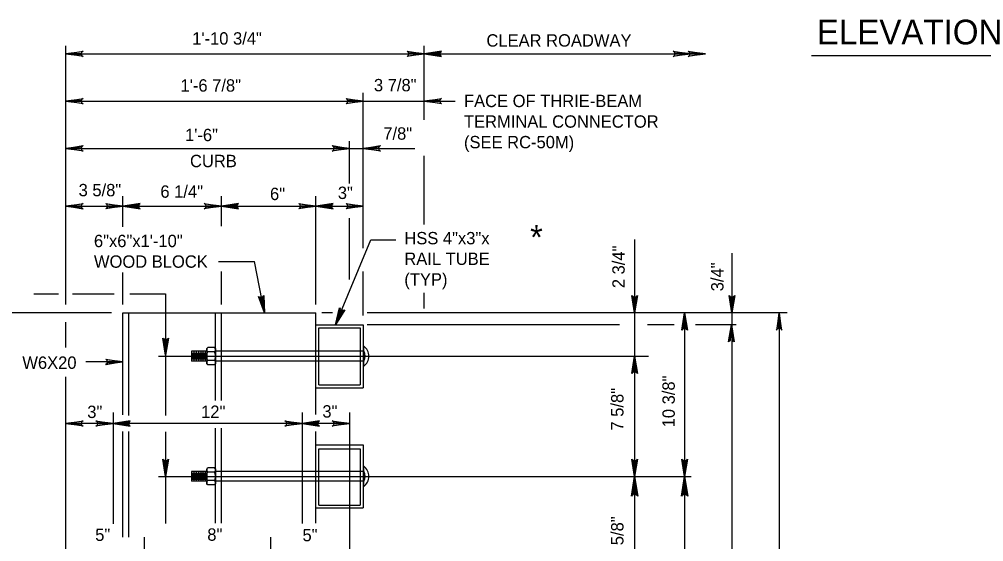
# Model space of a CAD drawing. Extents: x 641054 to 641910, y 298137 to 299325.
# Drawn here: x 641174.5 to 641408.6, y 298908.1 to 299034.9 of the extents above; entities that cross this region are included whole.
import ezdxf

# ---------------------------------------------------------------- set-up
doc = ezdxf.new("R2010")
doc.units = 0
for name, color, linetype in [('1', 7, 'Continuous'), ('2', 7, 'Continuous'), ('S-STEL', 7, 'Continuous')]:
    doc.layers.add(name, color=color, linetype=linetype)

msp = doc.modelspace()

# ---------------------------------------------------------------- linework, layer by layer
at = {"layer": '1'}
for p, q in [((641185.81, 298965.69), (641185.81, 299028.44)), ((641272.83, 299010.46), (641272.83, 299028.44)), ((641185.81, 299026.49), (641341.06, 299026.49)), ((641258.01, 298979.34), (641258.01, 299016.98)), ((641185.81, 299015.01), (641280.3, 299015.01)), ((641185.81, 299003.53), (641270.5, 299003.53)), ((641254.66, 298995.06), (641254.66, 299005.33)), ((641272.83, 298985.11), (641272.83, 299001.75)), ((641199.67, 298984.49), (641199.67, 298991.92)), ((641223.58, 298984.63), (641223.58, 298991.92)), ((641246.53, 298965.69), (641246.53, 298991.92)), ((641185.81, 298989.5), (641258.01, 298989.5)), ((641254.66, 298971.7), (641254.66, 298986.61)), ((641251.29, 298960.76), (641259.85, 298981.32)), ((641259.85, 298981.32), (641265.95, 298981.32)), ((641323.89, 298981.43), (641323.89, 298843.61)), ((641347.51, 298978.15), (641347.51, 298843.61)), ((641222.86, 298976.11), (641231.63, 298976.11)), ((641234.01, 298963.63), (641231.63, 298976.11)), ((641199.67, 298965.69), (641199.67, 298973.42)), ((641223.58, 298965.69), (641223.58, 298973.68)), ((641258.01, 298963.01), (641258.01, 298973.68)), ((641272.83, 298964.67), (641272.83, 298968.48)), ((641178.01, 298968.27), (641183.99, 298968.27)), ((641187.45, 298968.27), (641197.53, 298968.27)), ((641201.31, 298968.27), (641210.04, 298968.27)), ((641210.04, 298968.27), (641210.04, 298938.73)), ((641196.92, 298963.63), (641167.34, 298963.63)), ((641250.55, 298963.63), (641247.96, 298963.63)), ((641320.2, 298963.63), (641258.96, 298963.63)), ((641360.9, 298963.63), (641320.2, 298963.63)), ((641336.03, 298963.63), (641336.03, 298843.61)), ((641358.98, 298963.63), (641358.98, 298843.61)), ((641185.81, 298955.24), (641185.81, 298961.34)), ((641320.2, 298960.76), (641258.96, 298960.76)), ((641333.5, 298960.76), (641327.02, 298960.76)), ((641348.55, 298960.76), (641338.66, 298960.76)), ((641220.01, 298954.32), (641216.31, 298954.32)), ((641216.31, 298954.32), (641216.31, 298951.93)), ((641216.86, 298954.32), (641216.86, 298951.93)), ((641217.42, 298954.32), (641217.42, 298951.93)), ((641217.98, 298954.32), (641217.98, 298951.93)), ((641218.54, 298954.32), (641218.54, 298951.93)), ((641219.1, 298954.32), (641219.1, 298951.93)), ((641219.66, 298954.32), (641219.66, 298951.93)), ((641220.01, 298954.92), (641220.01, 298954.68)), ((641220.01, 298954.68), (641220.01, 298953.13)), ((641221.91, 298955.2), (641220.25, 298955.2)), ((641222.14, 298954.93), (641222.14, 298951.33)), ((641247.25, 298954.32), (641222.14, 298954.32)), ((641257.29, 298954.32), (641247.25, 298954.32)), ((641258.02, 298954.32), (641257.29, 298954.32)), ((641258.01, 298954.76), (641258.01, 298953.19)), ((641258.12, 298954.3), (641258.12, 298955.58)), ((641258.12, 298954.3), (641258.14, 298954.3)), ((641258.12, 298954.3), (641258.12, 298951.95)), ((641258.14, 298954.3), (641258.14, 298955.58)), ((641220.01, 298951.93), (641216.31, 298951.93)), ((641216.58, 298953.96), (641216.58, 298952.32)), ((641217.14, 298953.96), (641217.14, 298952.32)), ((641217.7, 298953.96), (641217.7, 298952.32)), ((641218.26, 298953.96), (641218.26, 298952.32)), ((641218.82, 298953.96), (641218.82, 298952.32)), ((641219.38, 298953.96), (641219.38, 298952.32)), ((641219.94, 298953.96), (641219.94, 298952.32)), ((641220.01, 298953.13), (641220.01, 298951.57)), ((641221.91, 298954.16), (641220.25, 298954.16)), ((641221.91, 298952.09), (641220.25, 298952.09)), ((641247.25, 298951.93), (641222.14, 298951.93)), ((641257.29, 298951.93), (641247.25, 298951.93)), ((641258.02, 298951.93), (641257.28, 298951.93)), ((641258.12, 298950.68), (641258.12, 298951.95)), ((641258.14, 298950.68), (641258.14, 298951.95)), ((641199.67, 298951.73), (641190.68, 298951.73)), ((641220.01, 298951.57), (641220.01, 298951.33)), ((641221.91, 298951.06), (641220.25, 298951.06)), ((641185.81, 298900.89), (641185.81, 298948.15)), ((641197.28, 298939.43), (641197.28, 298912.42)), ((641243.19, 298939.43), (641243.19, 298912.53)), ((641254.66, 298939.43), (641254.66, 298880.61)), ((641254.66, 298936.79), (641185.81, 298936.79)), ((641210.04, 298934.74), (641210.04, 298912.5)), ((641258.12, 298925.14), (641258.12, 298926.41)), ((641258.14, 298925.14), (641258.14, 298926.41)), ((641220.01, 298925.16), (641216.31, 298925.16)), ((641216.31, 298925.16), (641216.31, 298922.77)), ((641216.58, 298924.79), (641216.58, 298923.16)), ((641216.86, 298925.16), (641216.86, 298922.77)), ((641217.14, 298924.79), (641217.14, 298923.16)), ((641217.42, 298925.16), (641217.42, 298922.77)), ((641217.7, 298924.79), (641217.7, 298923.16)), ((641217.98, 298925.16), (641217.98, 298922.77)), ((641218.26, 298924.79), (641218.26, 298923.16)), ((641218.54, 298925.16), (641218.54, 298922.77)), ((641218.82, 298924.79), (641218.82, 298923.16)), ((641219.1, 298925.16), (641219.1, 298922.77)), ((641219.38, 298924.79), (641219.38, 298923.16)), ((641219.66, 298925.16), (641219.66, 298922.77)), ((641219.94, 298924.79), (641219.94, 298923.16)), ((641220.01, 298925.75), (641220.01, 298925.51)), ((641220.01, 298925.51), (641220.01, 298923.96)), ((641220.01, 298923.96), (641220.01, 298922.41)), ((641221.91, 298926.03), (641220.25, 298926.03)), ((641221.91, 298925), (641220.25, 298925)), ((641222.14, 298925.76), (641222.14, 298922.16)), ((641247.25, 298925.16), (641222.14, 298925.16)), ((641257.29, 298925.16), (641247.25, 298925.16)), ((641258.02, 298925.16), (641257.29, 298925.16)), ((641258.01, 298925.6), (641258.01, 298924.02)), ((641258.12, 298925.14), (641258.14, 298925.14)), ((641258.12, 298925.14), (641258.12, 298922.79)), ((641220.01, 298922.77), (641216.31, 298922.77)), ((641220.01, 298922.41), (641220.01, 298922.17)), ((641221.91, 298922.93), (641220.25, 298922.93)), ((641221.91, 298921.89), (641220.25, 298921.89)), ((641247.25, 298922.77), (641222.14, 298922.77)), ((641257.29, 298922.77), (641247.25, 298922.77)), ((641258.02, 298922.77), (641257.29, 298922.77)), ((641258.12, 298921.51), (641258.12, 298922.79)), ((641258.14, 298921.51), (641258.14, 298922.79))]:
    msp.add_line(p, q, dxfattribs=at)
for points in [[(641250.69, 299004.03), (641250.84, 299003.75), (641254.66, 299003.53), (641250.69, 299004.03), (641250.48, 299004.21), (641254.66, 299003.53), (641250.84, 299003.35), (641250.7, 299003.06), (641254.66, 299003.53), (641250.48, 299002.87), (641250.7, 299003.06)], [(641323.32, 298919.4), (641323.65, 298919.57), (641323.89, 298923.94), (641323.32, 298919.4), (641323.12, 298919.17), (641323.89, 298923.94), (641324.11, 298919.58), (641324.44, 298919.42), (641323.89, 298923.94), (641324.65, 298919.17), (641324.44, 298919.42)], [(641335.46, 298919.4), (641335.79, 298919.57), (641336.03, 298923.94), (641335.46, 298919.4), (641335.26, 298919.17), (641336.03, 298923.94), (641336.25, 298919.58), (641336.57, 298919.42), (641336.03, 298923.94), (641336.79, 298919.17), (641336.57, 298919.42)]]:
    msp.add_lwpolyline(points, dxfattribs=at)
for centre, radius, start, end in [((641258, 298954.44), 0.119, 272.7217, 0.0027), ((641256.33, 298953.13), 3.04, 306.3703, 53.6297), ((641256.33, 298953.13), 2.15, 326.9318, 33.0682), ((641258, 298951.81), 0.119, 359.9973, 87.2783), ((641256.33, 298923.96), 3.04, 306.3703, 53.6297), ((641258, 298925.27), 0.119, 272.7217, 0.0027), ((641256.33, 298923.96), 2.15, 326.9318, 33.0682), ((641258, 298922.65), 0.119, 359.9973, 87.2783)]:
    msp.add_arc(centre, radius, start, end, dxfattribs=at)
for points, degree in [([(641220.01, 298954.68), (641220.02, 298954.75), (641220.04, 298954.91), (641220.15, 298955.08), (641220.23, 298955.17), (641220.25, 298955.2)], 3), ([(641220.01, 298954.92), (641220.25, 298955.2)], 1), ([(641220.25, 298954.16), (641220.19, 298954.24), (641220.07, 298954.39), (641220.01, 298954.58), (641220.01, 298954.68), (641220.01, 298954.68)], 3), ([(641222.15, 298954.68), (641222.14, 298954.75), (641222.12, 298954.91), (641222.01, 298955.08), (641221.93, 298955.17), (641221.91, 298955.2)], 3), ([(641221.91, 298955.2), (641222.14, 298954.93)], 1), ([(641221.91, 298954.16), (641221.97, 298954.24), (641222.09, 298954.39), (641222.15, 298954.58), (641222.15, 298954.68), (641222.15, 298954.68)], 3), ([(641222.14, 298954.32), (641222.15, 298954.32)], 1), ([(641258, 298954.32), (641258, 298954.32), (641258.03, 298954.32), (641258.1, 298954.31), (641258.11, 298954.26), (641258.12, 298954.24)], 3), ([(641258, 298954.32), (641258, 298954.32)], 1), ([(641220.01, 298953.13), (641220.01, 298953.15), (641220.01, 298953.31), (641220.05, 298953.6), (641220.15, 298953.92), (641220.22, 298954.1), (641220.25, 298954.16)], 3), ([(641220.25, 298952.09), (641220.21, 298952.18), (641220.13, 298952.39), (641220.03, 298952.73), (641220.02, 298953), (641220.01, 298953.13)], 3), ([(641220.01, 298951.57), (641220.02, 298951.65), (641220.04, 298951.81), (641220.15, 298951.97), (641220.23, 298952.06), (641220.25, 298952.09)], 3), ([(641222.15, 298953.13), (641222.15, 298953.15), (641222.15, 298953.31), (641222.11, 298953.6), (641222.01, 298953.92), (641221.93, 298954.1), (641221.91, 298954.16)], 3), ([(641221.91, 298952.09), (641221.94, 298952.18), (641222.03, 298952.39), (641222.12, 298952.73), (641222.14, 298953), (641222.15, 298953.13)], 3), ([(641222.15, 298951.57), (641222.14, 298951.65), (641222.12, 298951.81), (641222.01, 298951.97), (641221.93, 298952.06), (641221.91, 298952.09)], 3), ([(641222.15, 298951.93), (641222.14, 298951.93)], 1), ([(641258.12, 298952.02), (641258.11, 298952), (641258.1, 298951.95), (641258.03, 298951.93), (641258, 298951.93), (641258, 298951.93)], 3), ([(641220.25, 298951.06), (641220.19, 298951.14), (641220.07, 298951.28), (641220.01, 298951.48), (641220.01, 298951.57), (641220.01, 298951.57)], 3), ([(641220.25, 298951.06), (641220.01, 298951.33)], 1), ([(641221.91, 298951.06), (641221.97, 298951.14), (641222.09, 298951.28), (641222.15, 298951.48), (641222.15, 298951.57), (641222.15, 298951.57)], 3), ([(641222.14, 298951.33), (641221.91, 298951.06)], 1), ([(641220.01, 298925.51), (641220.02, 298925.59), (641220.04, 298925.74), (641220.15, 298925.91), (641220.23, 298926), (641220.25, 298926.03)], 3), ([(641220.01, 298925.75), (641220.25, 298926.03)], 1), ([(641220.25, 298925), (641220.19, 298925.07), (641220.07, 298925.22), (641220.01, 298925.42), (641220.01, 298925.51), (641220.01, 298925.51)], 3), ([(641220.01, 298923.96), (641220.01, 298923.98), (641220.01, 298924.14), (641220.05, 298924.43), (641220.15, 298924.75), (641220.22, 298924.94), (641220.25, 298925)], 3), ([(641220.25, 298922.93), (641220.21, 298923.01), (641220.13, 298923.22), (641220.03, 298923.57), (641220.02, 298923.83), (641220.01, 298923.96)], 3), ([(641222.15, 298925.51), (641222.14, 298925.59), (641222.12, 298925.74), (641222.01, 298925.91), (641221.93, 298926), (641221.91, 298926.03)], 3), ([(641221.91, 298926.03), (641222.14, 298925.76)], 1), ([(641221.91, 298925), (641221.97, 298925.07), (641222.09, 298925.22), (641222.15, 298925.42), (641222.15, 298925.51), (641222.15, 298925.51)], 3), ([(641222.15, 298923.96), (641222.15, 298923.98), (641222.15, 298924.14), (641222.11, 298924.43), (641222.01, 298924.75), (641221.93, 298924.94), (641221.91, 298925)], 3), ([(641221.91, 298922.93), (641221.94, 298923.01), (641222.03, 298923.22), (641222.12, 298923.57), (641222.14, 298923.83), (641222.15, 298923.96)], 3), ([(641222.14, 298925.16), (641222.15, 298925.16)], 1), ([(641258, 298925.16), (641258, 298925.16), (641258.03, 298925.16), (641258.1, 298925.14), (641258.11, 298925.09), (641258.12, 298925.07)], 3), ([(641258, 298925.16), (641258, 298925.16)], 1), ([(641220.01, 298922.41), (641220.02, 298922.48), (641220.04, 298922.64), (641220.15, 298922.81), (641220.23, 298922.9), (641220.25, 298922.93)], 3), ([(641220.25, 298921.89), (641220.19, 298921.97), (641220.07, 298922.12), (641220.01, 298922.31), (641220.01, 298922.41), (641220.01, 298922.41)], 3), ([(641220.25, 298921.89), (641220.01, 298922.17)], 1), ([(641222.15, 298922.41), (641222.14, 298922.48), (641222.12, 298922.64), (641222.01, 298922.81), (641221.93, 298922.9), (641221.91, 298922.93)], 3), ([(641221.91, 298921.89), (641221.97, 298921.97), (641222.09, 298922.12), (641222.15, 298922.31), (641222.15, 298922.41), (641222.15, 298922.41)], 3), ([(641222.14, 298922.16), (641221.91, 298921.89)], 1), ([(641222.15, 298922.77), (641222.14, 298922.77)], 1), ([(641258.12, 298922.85), (641258.11, 298922.83), (641258.1, 298922.78), (641258.03, 298922.77), (641258, 298922.77), (641258, 298922.77)], 3)]:
    msp.add_open_spline(points, degree=degree, dxfattribs=at)
at = {"layer": '2'}
for p, q in [((641366.83, 299026.07), (641421.78, 299026.07)), ((641199.67, 298963.63), (641246.53, 298963.63)), ((641199.67, 298938.87), (641199.67, 298963.63)), ((641201.11, 298938.72), (641201.11, 298963.63)), ((641222.14, 298942.36), (641222.14, 298963.63)), ((641223.58, 298942.38), (641223.58, 298963.63)), ((641246.53, 298939.01), (641246.53, 298963.63)), ((641246.53, 298960.76), (641258.01, 298960.76)), ((641247.25, 298960.04), (641257.29, 298960.04)), ((641247.25, 298946.17), (641247.25, 298960.04)), ((641257.29, 298960.04), (641257.29, 298946.17)), ((641258.01, 298960.76), (641258.01, 298945.46)), ((641208.34, 298953.11), (641327.29, 298953.11)), ((641246.53, 298945.46), (641258.01, 298945.46)), ((641247.25, 298946.17), (641257.29, 298946.17)), ((641222.14, 298912.6), (641222.14, 298935.62)), ((641223.58, 298912.6), (641223.58, 298935.62)), ((641199.67, 298909.22), (641199.67, 298934.83)), ((641201.11, 298909.22), (641201.11, 298934.83)), ((641246.53, 298912.6), (641246.53, 298934.83)), ((641246.53, 298931.6), (641258.01, 298931.6)), ((641258.01, 298931.6), (641258.01, 298916.29)), ((641247.25, 298930.64), (641257.29, 298930.64)), ((641247.25, 298917.01), (641247.25, 298930.64)), ((641257.29, 298930.64), (641257.29, 298917.01)), ((641208.34, 298923.94), (641337.63, 298923.94)), ((641247.25, 298917.01), (641257.29, 298917.01)), ((641246.53, 298916.29), (641258.01, 298916.29)), ((641204.93, 298837.87), (641204.93, 298909.25)), ((641235.54, 298837.87), (641235.54, 298909.25))]:
    msp.add_line(p, q, dxfattribs=at)
for points in [[(641189.78, 299025.99), (641189.63, 299026.27), (641185.81, 299026.49), (641189.78, 299025.99), (641189.98, 299025.81), (641185.81, 299026.49), (641189.63, 299026.67), (641189.77, 299026.96), (641185.81, 299026.49), (641189.98, 299027.15), (641189.77, 299026.96)], [(641268.86, 299026.98), (641269, 299026.7), (641272.83, 299026.49), (641268.86, 299026.98), (641268.65, 299027.16), (641272.83, 299026.49), (641269.01, 299026.3), (641268.87, 299026.01), (641272.83, 299026.49), (641268.65, 299025.82), (641268.87, 299026.01)], [(641276.8, 299026.98), (641276.65, 299026.7), (641272.83, 299026.49), (641276.8, 299026.98), (641277.01, 299027.16), (641272.83, 299026.49), (641276.65, 299026.3), (641276.79, 299026.01), (641272.83, 299026.49), (641277.01, 299025.82), (641276.79, 299026.01)], [(641333.45, 299026.98), (641333.59, 299026.7), (641337.42, 299026.49), (641333.45, 299026.98), (641333.24, 299027.16), (641337.42, 299026.49), (641333.6, 299026.3), (641333.46, 299026.01), (641337.42, 299026.49), (641333.24, 299025.82), (641333.46, 299026.01)], [(641337.08, 299026.98), (641337.23, 299026.7), (641341.06, 299026.49), (641337.08, 299026.98), (641336.88, 299027.16), (641341.06, 299026.49), (641337.23, 299026.3), (641337.09, 299026.01), (641341.06, 299026.49), (641336.88, 299025.82), (641337.09, 299026.01)], [(641189.78, 299014.51), (641189.63, 299014.8), (641185.81, 299015.01), (641189.78, 299014.51), (641189.98, 299014.34), (641185.81, 299015.01), (641189.63, 299015.2), (641189.77, 299015.48), (641185.81, 299015.01), (641189.98, 299015.67), (641189.77, 299015.48)], [(641254.03, 299015.51), (641254.18, 299015.22), (641258.01, 299015.01), (641254.03, 299015.51), (641253.83, 299015.68), (641258.01, 299015.01), (641254.19, 299014.82), (641254.05, 299014.54), (641258.01, 299015.01), (641253.83, 299014.35), (641254.05, 299014.54)], [(641276.8, 299014.51), (641276.65, 299014.8), (641272.83, 299015.01), (641276.8, 299014.51), (641277.01, 299014.34), (641272.83, 299015.01), (641276.65, 299015.2), (641276.79, 299015.48), (641272.83, 299015.01), (641277.01, 299015.67), (641276.79, 299015.48)], [(641189.78, 299003.04), (641189.63, 299003.32), (641185.81, 299003.53), (641189.78, 299003.04), (641189.98, 299002.86), (641185.81, 299003.53), (641189.63, 299003.72), (641189.77, 299004.01), (641185.81, 299003.53), (641189.98, 299004.2), (641189.77, 299004.01)], [(641261.98, 299003.04), (641261.83, 299003.32), (641258.01, 299003.53), (641261.98, 299003.04), (641262.18, 299002.86), (641258.01, 299003.53), (641261.83, 299003.72), (641261.97, 299004.01), (641258.01, 299003.53), (641262.18, 299004.2), (641261.97, 299004.01)], [(641189.78, 298989), (641189.63, 298989.29), (641185.81, 298989.5), (641189.78, 298989), (641189.98, 298988.83), (641185.81, 298989.5), (641189.63, 298989.69), (641189.77, 298989.98), (641185.81, 298989.5), (641189.98, 298990.17), (641189.77, 298989.98)], [(641195.7, 298990), (641195.85, 298989.71), (641199.67, 298989.5), (641195.7, 298990), (641195.5, 298990.18), (641199.67, 298989.5), (641195.85, 298989.31), (641195.71, 298989.03), (641199.67, 298989.5), (641195.5, 298988.84), (641195.71, 298989.03)], [(641203.65, 298990), (641203.5, 298989.71), (641199.67, 298989.5), (641203.65, 298990), (641203.85, 298990.18), (641199.67, 298989.5), (641203.5, 298989.31), (641203.64, 298989.03), (641199.67, 298989.5), (641203.85, 298988.84), (641203.64, 298989.03)], [(641219.61, 298990), (641219.76, 298989.71), (641223.58, 298989.5), (641219.61, 298990), (641219.4, 298990.18), (641223.58, 298989.5), (641219.76, 298989.31), (641219.62, 298989.03), (641223.58, 298989.5), (641219.4, 298988.84), (641219.62, 298989.03)], [(641227.55, 298990), (641227.41, 298989.71), (641223.58, 298989.5), (641227.55, 298990), (641227.76, 298990.18), (641223.58, 298989.5), (641227.4, 298989.31), (641227.54, 298989.03), (641223.58, 298989.5), (641227.76, 298988.84), (641227.54, 298989.03)], [(641242.56, 298990), (641242.71, 298989.71), (641246.53, 298989.5), (641242.56, 298990), (641242.36, 298990.18), (641246.53, 298989.5), (641242.71, 298989.31), (641242.57, 298989.03), (641246.53, 298989.5), (641242.36, 298988.84), (641242.57, 298989.03)], [(641242.56, 298990), (641242.71, 298989.71), (641246.53, 298989.5), (641242.56, 298990), (641242.36, 298990.18), (641246.53, 298989.5), (641242.71, 298989.31), (641242.57, 298989.03), (641246.53, 298989.5), (641242.36, 298988.84), (641242.57, 298989.03)], [(641250.5, 298990), (641250.36, 298989.71), (641246.53, 298989.5), (641250.5, 298990), (641250.71, 298990.18), (641246.53, 298989.5), (641250.35, 298989.31), (641250.49, 298989.03), (641246.53, 298989.5), (641250.71, 298988.84), (641250.49, 298989.03)], [(641254.03, 298990), (641254.18, 298989.71), (641258.01, 298989.5), (641254.03, 298990), (641253.83, 298990.18), (641258.01, 298989.5), (641254.19, 298989.31), (641254.05, 298989.03), (641258.01, 298989.5), (641253.83, 298988.84), (641254.05, 298989.03)], [(641233.75, 298967.63), (641233.5, 298967.43), (641234.01, 298963.63), (641233.75, 298967.63), (641233.89, 298967.86), (641234.01, 298963.63), (641233.11, 298967.35), (641232.8, 298967.43), (641234.01, 298963.63), (641232.57, 298967.61), (641232.8, 298967.43)], [(641324.39, 298967.6), (641324.11, 298967.46), (641323.89, 298963.63), (641324.39, 298967.6), (641324.57, 298967.81), (641323.89, 298963.63), (641323.71, 298967.45), (641323.42, 298967.59), (641323.89, 298963.63), (641323.23, 298967.81), (641323.42, 298967.59)], [(641348, 298967.6), (641347.72, 298967.46), (641347.51, 298963.63), (641348, 298967.6), (641348.18, 298967.81), (641347.51, 298963.63), (641347.32, 298967.45), (641347.03, 298967.59), (641347.51, 298963.63), (641346.84, 298967.81), (641347.03, 298967.59)], [(641253.28, 298964.23), (641252.95, 298964.21), (641251.29, 298960.76), (641253.28, 298964.23), (641253.52, 298964.35), (641251.29, 298960.76), (641252.58, 298964.36), (641252.37, 298964.6), (641251.29, 298960.76), (641252.28, 298964.87), (641252.37, 298964.6)], [(641335.53, 298959.66), (641335.82, 298959.81), (641336.03, 298963.63), (641335.53, 298959.66), (641335.36, 298959.45), (641336.03, 298963.63), (641336.22, 298959.81), (641336.5, 298959.67), (641336.03, 298963.63), (641336.69, 298959.45), (641336.5, 298959.67)], [(641359.48, 298959.66), (641359.19, 298959.81), (641358.98, 298963.63), (641359.48, 298959.66), (641359.65, 298959.45), (641358.98, 298963.63), (641358.79, 298959.81), (641358.51, 298959.67), (641358.98, 298963.63), (641358.32, 298959.45), (641358.51, 298959.67)], [(641346.87, 298956.78), (641347.16, 298956.93), (641347.37, 298960.76), (641346.87, 298956.78), (641346.69, 298956.58), (641347.37, 298960.76), (641347.56, 298956.93), (641347.84, 298956.79), (641347.37, 298960.76), (641348.03, 298956.58), (641347.84, 298956.79)], [(641210.54, 298957.31), (641210.25, 298957.16), (641210.04, 298953.34), (641210.54, 298957.31), (641210.71, 298957.51), (641210.04, 298953.34), (641209.85, 298957.16), (641209.57, 298957.3), (641210.04, 298953.34), (641209.38, 298957.51), (641209.57, 298957.3)], [(641195.7, 298952.23), (641195.85, 298951.94), (641199.67, 298951.73), (641195.7, 298952.23), (641195.5, 298952.4), (641199.67, 298951.73), (641195.85, 298951.54), (641195.71, 298951.25), (641199.67, 298951.73), (641195.5, 298951.06), (641195.71, 298951.25)], [(641323.4, 298949.14), (641323.68, 298949.29), (641323.89, 298953.11), (641323.4, 298949.14), (641323.22, 298948.93), (641323.89, 298953.11), (641324.08, 298949.29), (641324.37, 298949.15), (641323.89, 298953.11), (641324.56, 298948.93), (641324.37, 298949.15)], [(641189.78, 298936.29), (641189.63, 298936.57), (641185.81, 298936.79), (641189.78, 298936.29), (641189.98, 298936.11), (641185.81, 298936.79), (641189.63, 298936.97), (641189.77, 298937.26), (641185.81, 298936.79), (641189.98, 298937.45), (641189.77, 298937.26)], [(641193.31, 298937.28), (641193.46, 298937), (641197.28, 298936.79), (641193.31, 298937.28), (641193.11, 298937.46), (641197.28, 298936.79), (641193.46, 298936.6), (641193.32, 298936.31), (641197.28, 298936.79), (641193.11, 298936.12), (641193.32, 298936.31)], [(641201.26, 298937.28), (641201.11, 298937), (641197.28, 298936.79), (641201.26, 298937.28), (641201.46, 298937.46), (641197.28, 298936.79), (641201.11, 298936.6), (641201.25, 298936.31), (641197.28, 298936.79), (641201.46, 298936.12), (641201.25, 298936.31)], [(641239.21, 298937.28), (641239.36, 298937), (641243.19, 298936.79), (641239.21, 298937.28), (641239.01, 298937.46), (641243.19, 298936.79), (641239.37, 298936.6), (641239.23, 298936.31), (641243.19, 298936.79), (641239.01, 298936.12), (641239.23, 298936.31)], [(641247.16, 298937.28), (641247.01, 298937), (641243.19, 298936.79), (641247.16, 298937.28), (641247.36, 298937.46), (641243.19, 298936.79), (641247.01, 298936.6), (641247.15, 298936.31), (641243.19, 298936.79), (641247.36, 298936.12), (641247.15, 298936.31)], [(641250.69, 298937.28), (641250.84, 298937), (641254.66, 298936.79), (641250.69, 298937.28), (641250.49, 298937.46), (641254.66, 298936.79), (641250.84, 298936.6), (641250.7, 298936.31), (641254.66, 298936.79), (641250.49, 298936.12), (641250.7, 298936.31)], [(641210.54, 298927.92), (641210.25, 298927.77), (641210.04, 298923.94), (641210.54, 298927.92), (641210.71, 298928.12), (641210.04, 298923.94), (641209.85, 298927.77), (641209.57, 298927.91), (641210.04, 298923.94), (641209.38, 298928.12), (641209.57, 298927.91)], [(641324.39, 298927.92), (641324.11, 298927.77), (641323.89, 298923.94), (641324.39, 298927.92), (641324.57, 298928.12), (641323.89, 298923.94), (641323.71, 298927.77), (641323.42, 298927.91), (641323.89, 298923.94), (641323.23, 298928.12), (641323.42, 298927.91)], [(641336.53, 298927.92), (641336.24, 298927.77), (641336.03, 298923.94), (641336.53, 298927.92), (641336.7, 298928.12), (641336.03, 298923.94), (641335.84, 298927.77), (641335.56, 298927.91), (641336.03, 298923.94), (641335.37, 298928.12), (641335.56, 298927.91)]]:
    msp.add_lwpolyline(points, dxfattribs=at)
at = {"layer": 'S-STEL'}
for p, q in [((641258.02, 298954.32), (641257.3, 298954.32)), ((641258.02, 298951.93), (641257.3, 298951.93)), ((641258.02, 298925.16), (641257.3, 298925.16))]:
    msp.add_line(p, q, dxfattribs=at)

# ---------------------------------------------------------------- texts
at = {"layer": '2'}
for s, height, p in [('ELEVATION', 6, (641368.12, 299028.77)), ('1\'-10 3/4"', 3, (641216.49, 299028.72)), ('CLEAR ROADWAY', 3.0001, (641287.91, 299028.23)), ('1\'-6 7/8"', 3, (641213.65, 299017.31)), ('3 7/8"', 3, (641260.6, 299017.39)), ('FACE OF THRIE-BEAM', 3.0001, (641282.46, 299013.56)), ('TERMINAL CONNECTOR', 3.0001, (641282.46, 299008.56)), ('1\'-6"', 3, (641214.75, 299005.3)), ('7/8"', 3, (641262.88, 299005.65)), ('(SEE RC-50M)', 3.0001, (641282.46, 299003.56)), ('CURB', 3, (641215.95, 298998.98)), ('3 5/8"', 3, (641188.91, 298991.92)), ('6 1/4"', 3, (641208.76, 298991.57)), ('3"', 3, (641251.84, 298991.26)), ('6"', 3, (641235.37, 298991)), ('*', 5.88, (641298.52, 298979.05)), ('6"x6"x1\'-10"', 3.0001, (641192.63, 298979.58)), ('HSS 4"x3"x  ', 3.0001, (641267.98, 298980.26)), ('RAIL TUBE', 3, (641267.98, 298975.26)), ('WOOD BLOCK', 3, (641192.63, 298974.58)), ('(TYP)', 3, (641267.98, 298970.26)), ('W6X20', 3, (641175.25, 298950.05)), ('3"', 3, (641191.01, 298938.12)), ('12"', 3, (641218.65, 298938.14)), ('3"', 3, (641248.09, 298938.23)), ('5"', 3, (641192.94, 298908.29)), ('8"', 3, (641220.15, 298908.34)), ('5"', 3, (641243.26, 298908.22))]:
    msp.add_text(s, height=height, dxfattribs=at).set_placement(p)
for s, p in [('2 3/4"', (641321.47, 298969.62)), ('3/4"', (641345.46, 298968.87)), ('10 3/8"', (641333.63, 298935.85)), ('7 5/8"', (641321.18, 298935.07)), ('7 5/8"', (641321.18, 298903.91))]:
    msp.add_text(s, height=3, rotation=90, dxfattribs=at).set_placement(p)

doc.saveas('drawing.dxf')
